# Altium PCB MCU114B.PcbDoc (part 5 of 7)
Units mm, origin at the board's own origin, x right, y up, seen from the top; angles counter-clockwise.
Board outline 105.51 x 58.76 mm, 8 copper layers (Top Layer, GND 2, Signal Layer 3, Power 4, Power 5, Signal Layer 6, GND 7, Bottom), stack 1.554 mm thick; 444 components, 418 nets, 1811 pads, 981 vias.
Unrouted connection lines stored in the file: 3.
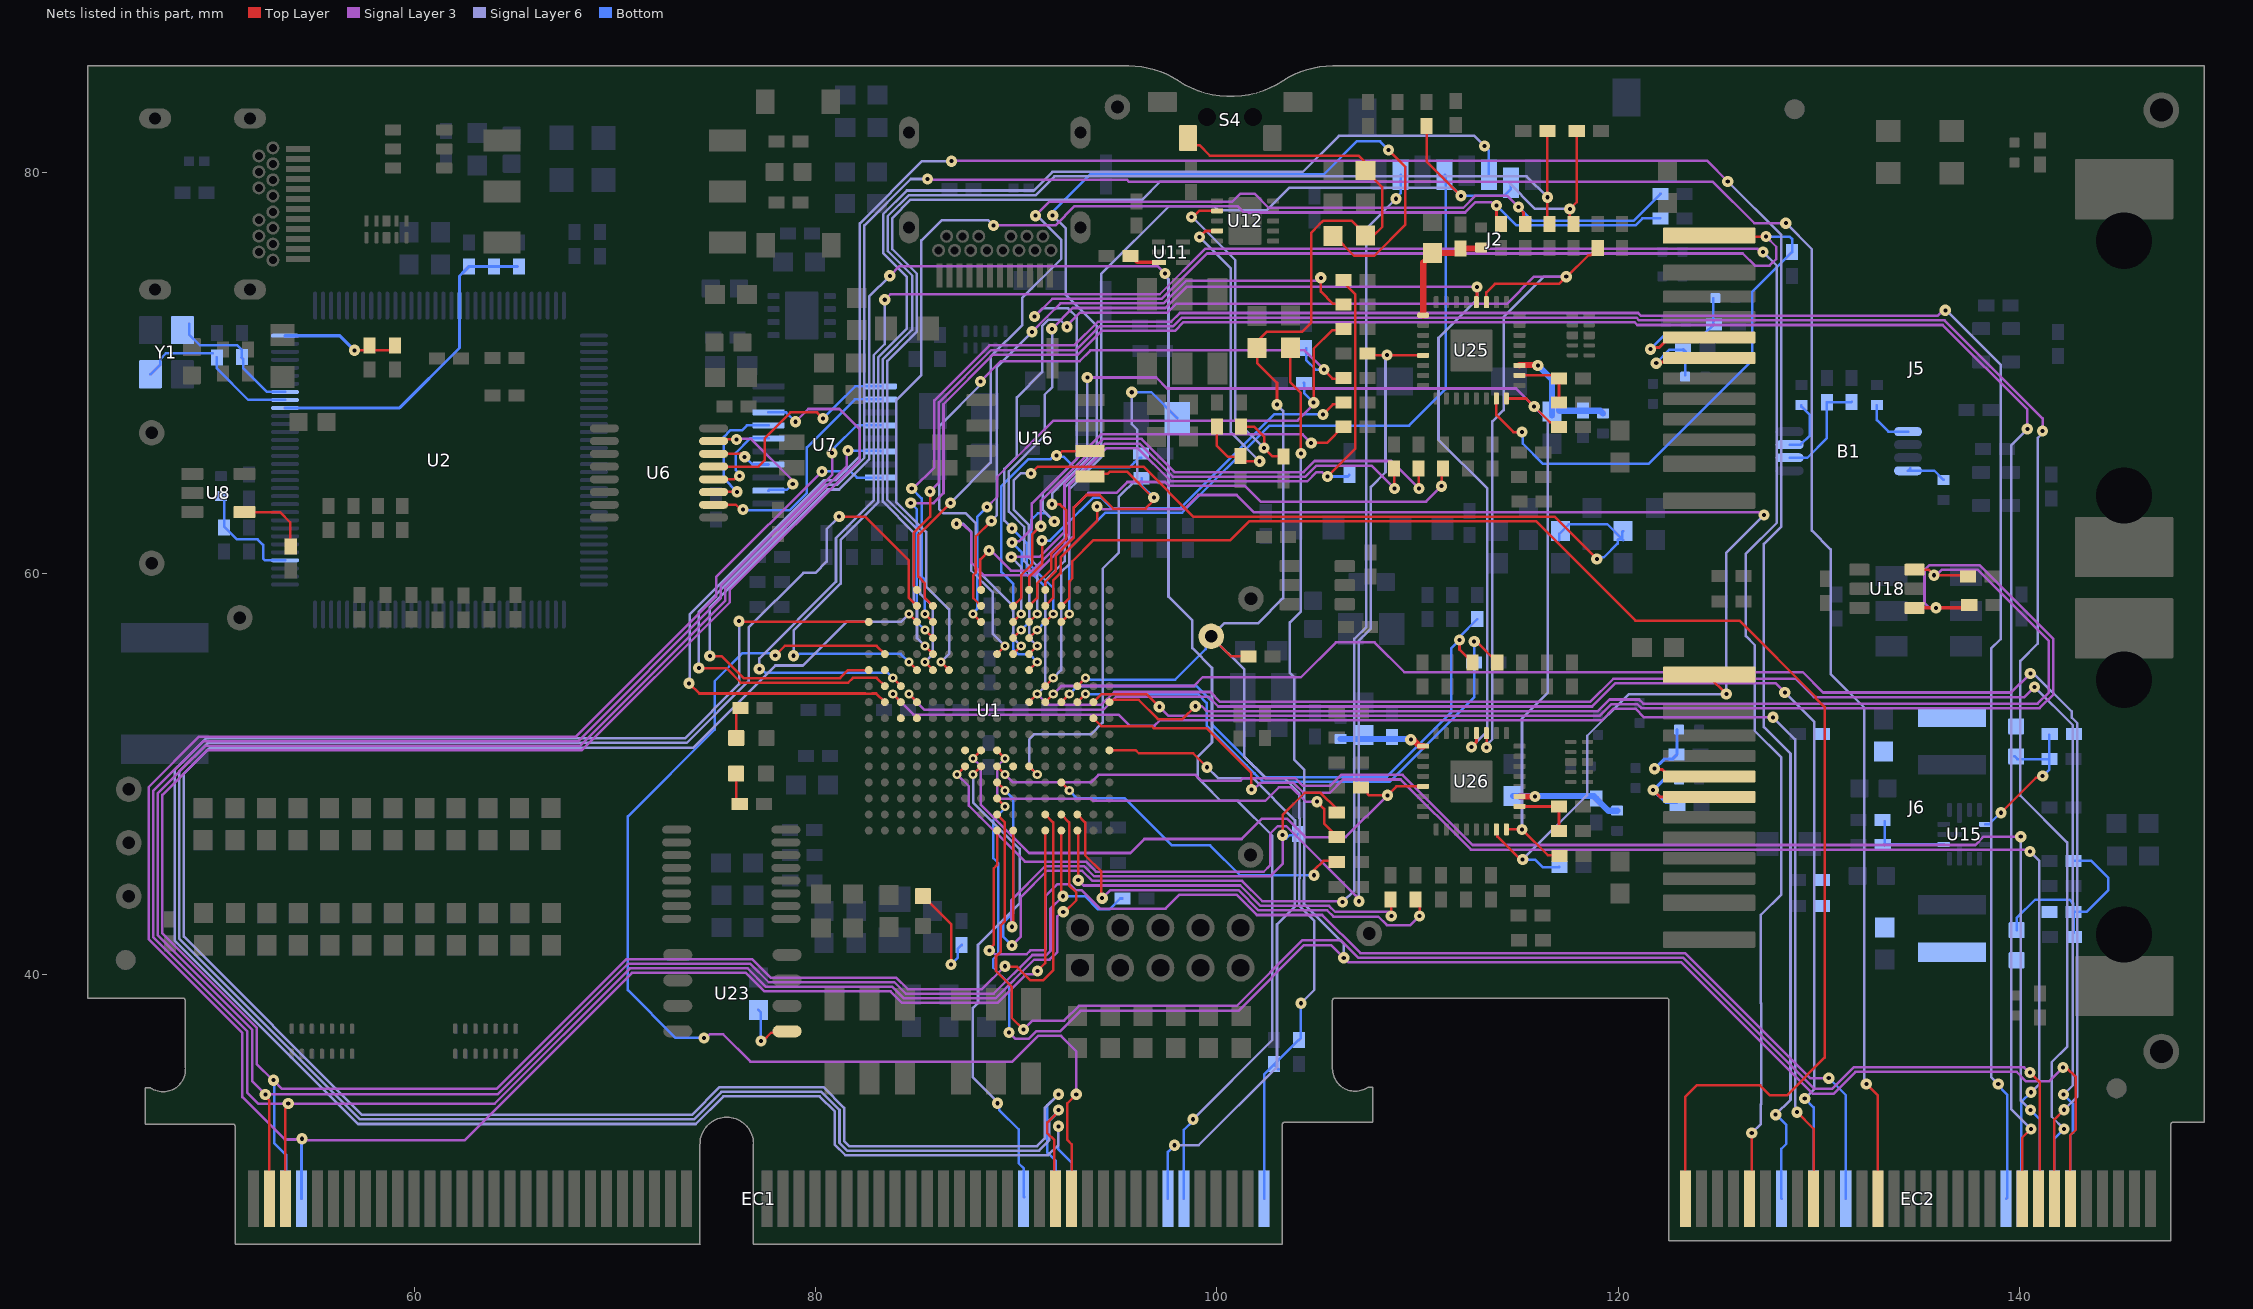
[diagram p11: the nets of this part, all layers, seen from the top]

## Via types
v1: diameter 0.559, hole 0.203, Top Layer to Bottom, tented both sides, 810 vias
v2: diameter 0.457, hole 0.203, Top Layer to Bottom, tented both sides, 153 vias
v3: diameter 0.5, hole 0.2, Top Layer to Bottom, tented both sides, 10 vias
v4: diameter 0.5, hole 0.2, Top Layer to Bottom, tented bottom, 4 vias
v5: diameter 0.5, hole 0.2, Top Layer to Bottom, tented top, 4 vias

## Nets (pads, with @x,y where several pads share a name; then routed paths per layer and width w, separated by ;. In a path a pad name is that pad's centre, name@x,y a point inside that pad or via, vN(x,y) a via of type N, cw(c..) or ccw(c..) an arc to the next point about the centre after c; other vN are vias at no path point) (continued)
MCU_GPIO93: EC2.162 U1.C5 | length 110.4
  Top Layer w0.127: v2(85.441,57.995) U1.C5@85.841,57.595
  Signal Layer 3 w0.127: v1(84.785,64.249) 84.853,64.249 85.911,65.307 85.911,68.639 88.653,71.381 90.23,71.381 92.881,71.381 94.062,72.562 97.718,72.562 98.155,73 121.006,73 121.147,72.859 135.926,72.859 136.201,73.133 v1(136.318,73.133)
  Signal Layer 6 w0.127: v1(136.318,73.133) 136.368,73.133 139.074,70.427 139.074,56.732 138.606,56.264 138.606,34.904 v1(138.959,34.551)
  Bottom w0.127: v1(84.785,64.249) 85.278,63.756 85.278,59.865 85.441,59.701 v2(85.441,57.995) ; v1@138.883,34.551 139.404,34.03 139.404,28.885 EC2.162@139.355,28.836
MCU_GPIO94: EC2.163 U1.D5 | length 111.1
  Top Layer w0.127: v2(85.441,57.195) U1.D5@85.841,56.795 ; EC2.163@140.155,28.836 140.155,31.886 v1(140.585,32.316)
  Signal Layer 3 w0.127: v1(84.736,63.525) 85.877,63.525 86.368,64.016 86.368,68.45 88.842,70.924 90.041,70.924 93.07,70.924 94.252,72.105 97.907,72.105 98.344,72.542 120.817,72.542 120.958,72.402 136.186,72.402 140.407,68.18 v1(140.407,67.215)
  Signal Layer 6 w0.127: v1(140.407,67.215) 139.608,66.416 139.608,33.293 v1(140.585,32.316)
  Bottom w0.127: v1@84.836,63.424 85.035,63.225 85.035,57.601 v2(85.441,57.195)
MCU_GPIO95: EC2.168 U1.A4 | length 109.9
  Top Layer w0.127: U1.A4@85.041,59.195 85.041,59.247 84.883,59.406 84.883,62.027 85.7,62.844 v1(85.7,64.107)
  Signal Layer 3 w0.127: v1(85.7,64.107) 86.14,64.547 86.14,68.545 88.748,71.152 90.136,71.152 92.975,71.152 94.157,72.334 97.812,72.334 98.25,72.771 120.912,72.771 121.053,72.63 136.28,72.63 141.169,67.742 v1(141.169,67.114)
  Signal Layer 6 w0.127: v1(141.169,67.114) 141.169,67.014 140.928,66.773 140.928,56.516 140.065,55.653 140.065,48.93 142.388,46.606 142.388,36.411 141.626,35.649 141.626,32.925 v1(142.236,32.316)
  Bottom w0.127: EC2.168@141.755,28.836 141.755,31.835 v1(142.236,32.316)
MCU_GPIO96: EC1.93 U1.B4 | length 112.3
  Top Layer w0.127: v1(81.168,62.852) 82.462,62.852 84.632,60.682 84.632,59.033 84.632,58.804 U1.B4@85.041,58.395 ; EC1.93@91.957,28.836 91.893,28.9 91.893,31.756 91.55,32.099 91.55,32.643 92.096,33.189 v1(92.096,33.255)
  Signal Layer 6 w0.127: v1@81.085,62.759 80.543,62.217 80.543,60.604 79.981,60.042 79.377,60.042 76.653,57.317 76.653,54.649 73.566,51.562 49.694,51.562 48.26,50.128 48.26,41.808 57.277,32.791 73.921,32.791 75.299,34.17 80.284,34.17 81.182,33.272 81.182,31.619 81.565,31.236 91.132,31.236 91.651,31.755 91.651,32.743 92.096,33.189 v1(92.096,33.255)
MCU_GPIO97: EC1.94 U1.C4 | length 105.8
  Top Layer w0.127: v2(84.641,57.995) U1.C4@85.041,57.595
  Signal Layer 6 w0.127: v2(84.641,57.995) 84.241,57.595 81.53,57.595 79.358,55.423 77.986,55.423 73.896,51.333 49.789,51.333 48.489,50.033 48.489,41.903 57.371,33.02 73.826,33.02 75.205,34.398 80.378,34.398 81.41,33.366 81.41,31.714 81.659,31.465 91.037,31.465 91.41,31.838 91.41,33.357 v1(92.096,34.043)
  Bottom w0.127: EC1.94@91.957,28.836 91.969,28.848 91.969,30.715 91.55,31.135 91.55,33.497 v1(92.096,34.043)
MCU_GPIO98: EC1.95 U1.E2 | length 59.1
  Top Layer w0.127: v1(77.978,55.931) 78.452,56.404 83.032,56.404 U1.E2@83.441,55.995 ; EC1.95@92.757,28.836 92.757,31.553 92.541,31.77 92.541,33.598 v1(92.985,34.043)
  Signal Layer 3 w0.127: v1(74.422,36.855) 74.534,36.855 74.712,37.033 75.387,37.033 76.746,35.674 89.802,35.674 91.084,36.957 92.227,36.957 92.985,36.199 v1(92.985,34.043)
  Bottom w0.127: v1(74.422,36.855) 73.011,36.855 70.631,39.236 70.631,47.895 74.964,52.228 74.964,54.648 76.355,56.039 77.87,56.039 v1(77.978,55.931)
MCU_GPIO99: EC1.96 U1.C1 | length 103.9
  Top Layer w0.127: v1(76.175,57.633) 76.212,57.595 U1.C1@82.641,57.595
  Signal Layer 6 w0.127: v1(76.175,57.633) 76.175,54.494 73.471,51.791 49.599,51.791 48.031,50.223 48.031,41.713 57.182,32.563 74.016,32.563 75.394,33.941 80.189,33.941 80.953,33.177 80.953,31.524 81.47,31.008 91.586,31.008 92.095,31.516 v1(92.095,32.448) v1@92.095,32.559
  Bottom w0.127: v1@92.096,32.558 92.096,31.297 92.757,30.636 EC1.96@92.757,28.836
MCU_GPIO100: J2.3 U1.F4 | length 64.7
  Top Layer w0.127: v2(84.641,55.595) U1.F4@85.041,55.195
  Signal Layer 6 w0.127: v1(78.894,55.909) 78.894,57.163 81.238,59.506 81.238,61.687 83.117,63.566 83.117,70.798 84.547,72.228 84.547,74.801 83.359,75.99 83.359,77.923 84.544,79.108 90.875,79.108 91.803,80.035 104.281,80.035 106.079,81.833 112.833,81.833 v1(113.335,81.331)
  Bottom w0.127: v1(78.894,55.909) 78.977,55.992 79.175,55.992 79.184,56.001 84.235,56.001 v2(84.641,55.595) ; v1(113.335,81.331) 113.557,81.108 J2.3@113.557,79.893
MCU_GPIO101: J2.7 U1.N9 | length 66.1
  Top Layer w0.127: U1.N9@89.041,49.595 89.43,49.206 v2@89.43,49.192
  Signal Layer 3 w0.127: v1(89.785,41.47) 89.792,41.47 90.229,41.907 90.229,43.885 91.535,45.191 93.282,45.191 93.79,44.683 101.258,44.683 102.272,43.669 106.226,43.669 v1(106.267,43.628)
  Signal Layer 6 w0.127: v1(106.267,43.628) 106.854,44.214 106.854,56.757 107.45,57.354 107.45,77.21 v1(108.936,78.696)
  Bottom w0.127: v2(89.441,49.195) 89.841,48.795 89.841,48.28 89.841,48.121 ; v1(89.785,41.47) 89.34,41.915 89.34,42.584 89.841,43.085 89.841,48.121 ; v1(108.936,78.696) 108.936,78.749 109.157,78.97 J2.7@109.157,79.893
MCU_GPIO102: J2.5 U1.C13 | length 36.6
  Top Layer w0.127: U1.C13@92.241,57.595 v2(92.641,57.995)
  Bottom w0.127: v2(92.641,57.995) 92.641,61.248 94.436,63.043 98.273,63.043 102.616,67.386 109.584,67.386 111.4,69.202 111.4,78.721 111.4,79.85 J2.5@111.357,79.893
MCU_GPIO103: J2.2 R36.1 U1.G12 | length 48.9
  Top Layer w0.127: U1.G12@91.441,54.395 v2(91.841,54.795) ; R36.1@110.452,82.323 110.452,80.556 v1(112.166,78.842)
  Signal Layer 6 w0.127: v2(91.841,54.795) 92.235,55.189 92.235,60.082 92.642,60.489 92.642,64.211 94.23,65.798 94.23,74.94 97.61,78.321 99.865,78.321 100.062,78.124 102.49,78.124 103.602,79.235 111.773,79.235 v1(112.166,78.842)
  Bottom w0.127: v1(112.166,78.842) 114.321,78.842 114.657,79.178 J2.2@114.657,79.493
MCU_GPIO104: EC2.121 U1.B13 | length 75.4
  Top Layer w0.127: U1.B13@92.241,58.395 92.642,58.795 92.641,59.622 92.788,59.768 92.788,60.618 93.842,61.671 100.675,61.671 101.609,62.605 115.931,62.605 120.872,57.665 126.056,57.665 129.855,53.865 129.855,53.808 130.302,53.361 130.302,35.876 128.418,33.992 127.58,33.992 127.081,34.491 123.922,34.491 123.355,33.923 EC2.121@123.355,28.836
MCU_GPIO105: EC1.108 U1.L16 | length 32.9
  Top Layer w0.127: U1.L16@94.641,51.195 95.956,51.195 96.103,51.048 97.995,51.048 98.814,51.048 v1(99.513,50.35)
  Signal Layer 6 w0.127: v1(97.887,31.503) 99.092,31.503 102.997,35.408 102.997,42.52 103.886,43.409 103.886,44.907 103.894,44.916 103.894,47.701 101.792,49.804 100.059,49.804 v1(99.513,50.35)
  Bottom w0.127: EC1.108@97.557,28.836 97.557,31.173 v1(97.887,31.503)
MCU_GPIO106: EC1.110 U1.F1 | length 96.9
  Top Layer w0.127: v1(74.717,55.896) 75.295,55.896 76.398,54.793 81.209,54.793 81.61,55.194 81.929,55.194 ; 81.93,55.195 U1.F1@82.641,55.195
  Signal Layer 3 w0.127: v1(83.693,74.854) 84.176,75.336 97.043,75.336 v1(97.416,74.963)
  Signal Layer 6 w0.127: v1(74.717,55.896) 74.717,58.334 80.582,64.199 81.161,64.199 82.66,65.697 82.66,73.821 v1(83.693,74.854) ; v1(97.416,74.963) 97.416,74.847 97.587,74.676 97.587,58.854 98.776,57.665 98.776,56.287 99.754,55.309 99.754,51.588 99.034,50.867 99.034,49.832 99.399,49.467 100.192,48.673 101.03,48.673 102.768,46.935 102.768,36.765 v1(98.802,32.798)
  Bottom w0.127: EC1.110@98.357,28.836 98.357,32.277 98.802,32.722 v1(98.802,32.798)
MCU_GPIO107: U1.F2
MCU_GPIO108: EC2.145 U1.G2 | length 134
  Top Layer w0.127: v1(74.168,55.296) 75.54,55.296 76.271,54.564 81.615,54.564 81.855,54.804 83.032,54.804 U1.G2@83.441,54.395 ; v1(132.381,34.551) 132.955,33.977 EC2.145@132.955,28.836
  Signal Layer 3 w0.127: v1(85.573,79.68) 85.604,79.649 95.507,79.649 95.602,79.553 124.717,79.553 126.793,77.477 v1(128.367,77.477)
  Signal Layer 6 w0.127: v1(74.168,55.296) 74.168,58.108 80.487,64.427 81.067,64.427 82.423,65.783 82.423,77.368 84.735,79.68 v1(85.573,79.68) ; v1(128.367,77.477) 129.667,76.177 129.667,62.15 130.603,61.214 130.603,54.998 132.283,53.317 132.283,34.648 v1(132.381,34.551)
MCU_GPIO109: EC2.129 U1.G3 | length 122.8
  Top Layer w0.127: v2(83.841,54.795) U1.G3@84.241,54.395 ; EC2.129@126.555,28.836 126.666,28.947 v1(126.666,32.112)
  Signal Layer 3 w0.127: v1(83.439,73.66) 83.451,73.66 83.725,73.934 97.149,73.934 99.41,76.195 126.964,76.195 127.112,76.048 v1(127.229,76.048)
  Signal Layer 6 w0.127: v1(77.186,55.252) 77.186,55.778 81.009,59.601 81.009,61.781 82.889,63.661 82.889,70.893 83.439,71.443 v1(83.439,73.66) ; v1(126.666,32.112) 127.127,32.574 127.127,33.545 127.135,33.554 127.135,38.588 127.127,38.596 127.127,42.995 128.143,44.011 128.143,50.842 126.818,52.167 126.818,56.443 126.373,56.888 126.373,60.999 127.914,62.54 127.914,75.362 v1(127.229,76.048)
  Bottom w0.127: v1(77.186,55.252) 77.292,55.252 77.477,55.067 83.569,55.067 v2(83.841,54.795)
MCU_GPIO110: EC2.134 U1.H2 | length 135.3
  Top Layer w0.127: v1(73.685,54.534) 74.192,54.027 82.457,54.027 82.48,54.004 82.803,54.004 82.826,54.027 83.009,54.027 U1.H2@83.441,53.595
  Signal Layer 3 w0.127: v1(86.766,80.569) 86.779,80.581 124.45,80.581 v1(125.472,79.56)
  Signal Layer 6 w0.127: v1(73.685,54.534) 73.724,54.572 73.724,57.987 80.392,64.656 80.972,64.656 82.194,65.878 82.194,77.462 85.301,80.569 v1(86.766,80.569) ; v1(125.472,79.56) 128.143,76.888 128.143,62.349 127.275,61.481 127.275,52.356 128.278,51.353 128.6,51.031 128.6,33.768 v1(127.859,33.027)
  Bottom w0.127: v1(127.859,33.027) 127.885,33.027 128.393,32.519 128.393,31.579 128.139,31.325 128.139,28.852 EC2.134@128.155,28.836
MCU_GPIO111: EC2.137 U1.H3 | length 70.5
  Top Layer w0.127: v2(83.841,53.995) U1.H3@84.241,53.595 ; v1(128.926,33.154) 129.755,32.325 EC2.137@129.755,28.836
  Signal Layer 3 w0.127: v2(83.841,53.995) 84.864,52.972 95.093,52.972 95.64,52.426 96.897,52.426 97.166,52.694 119.187,52.694 119.764,53.271 120.864,53.271 121.296,52.839 v1(127.732,52.839)
  Signal Layer 6 w0.127: v1(127.732,52.839) 128.829,51.742 128.829,33.444 128.843,33.429 128.843,33.236 v1(128.926,33.154)
MCU_GPIO112: EC2.138 U1.H4 | length 71.9
  Top Layer w0.127: v2(84.641,53.995) U1.H4@85.041,53.595
  Signal Layer 3 w0.127: v2(84.641,53.995) 85.423,53.214 94.334,53.214 94.994,53.873 99.575,53.873 100.068,53.38 118.705,53.38 119.859,54.534 127.866,54.534 v1(128.317,54.083)
  Signal Layer 6 w0.127: v1(128.317,54.083) 129.794,52.606 129.794,34.315 v1(129.311,33.833)
  Bottom w0.127: v1(129.311,33.833) 129.755,33.39 EC2.138@129.755,28.836
MCU_GPIO113: U1.J3 | length 0
MCU_GPIO114: U1.J4
MCU_GPIO115: EC2.169 R212.1 U1.P9 | length 110.3
  Top Layer w0.127: U1.P9@89.041,48.795 v2(89.441,48.395) ; R212.1@103.658,71.267 103.658,69.538 104.191,69.006 v1(104.191,65.989) ; v1(142.189,35.382) 142.344,35.382 142.824,34.902 142.824,32.275 142.555,32.006 EC2.169@142.555,28.836
  Signal Layer 3 w0.127: v1(89.638,37.124) 89.957,36.805 90.609,36.805 90.99,37.186 92.177,37.186 93.199,38.208 101.067,38.208 104.336,41.478 105.698,41.478 v1(106.326,40.85) 106.555,40.621 123.16,40.621 129.701,34.081 130.761,34.081 131.84,35.16 139.88,35.16 140.35,34.691 141.498,34.691 v1(142.189,35.382)
  Signal Layer 6 w0.127: v1(104.191,65.989) 104.191,58.12 103.64,57.57 103.64,55.059 103.85,54.849 103.85,50.735 104.352,50.234 104.352,44.718 104.343,44.709 104.343,43.531 106.326,41.548 v1(106.326,40.85)
  Bottom w0.127: v2(89.441,48.395) 89.441,48.306 88.849,47.713 88.849,45.817 89.098,45.568 89.098,41.034 88.849,40.785 88.849,40.354 89.638,39.565 v1(89.638,37.124) ; v1@89.56,37.16 v1@89.581,37.181
MCU_GPIO116: EC2.170 R78.1 U1.H11 | length 131.9
  Top Layer w0.127: U1.H11@90.641,53.595 v2(91.041,53.995) ; R78.1@105.871,76.829 106.849,75.851 107.844,75.851 109.398,77.405 109.398,80.289 v1(108.56,81.128)
  Signal Layer 3 w0.127: v2(91.041,53.995) 91.564,53.473 94.253,53.473 94.883,54.102 99.67,54.102 100.163,53.609 118.61,53.609 119.764,54.762 128.854,54.762 129.769,53.848 140.259,53.848 v1(140.767,54.356)
  Signal Layer 6 w0.127: v2(91.041,53.995) 91.448,54.401 91.448,59.666 92.414,60.632 92.414,64.306 94.001,65.893 94.001,72.369 92.47,73.901 92.47,77.208 v1(91.81,77.867) ; v1(140.767,54.356) 142.672,52.451 142.672,34.493 v1(142.215,34.036)
  Bottom w0.127: v1@91.722,77.955 93.678,79.911 105.326,79.911 106.968,81.554 108.134,81.554 v1(108.56,81.128) ; v1(142.215,34.036) 142.684,33.566 142.684,32.136 142.555,32.006 EC2.170@142.555,28.836
MCU_GPIO119: U1.M10
MCU_GPIO120: R85.2 U1.M11 | length 26.6
  Top Layer w0.127: U1.M11@90.641,50.395 v2(91.041,49.995)
  Signal Layer 6 w0.127: v2(91.041,49.995) 90.648,50.389 90.648,51.758 90.878,51.989 93.604,51.989 93.717,51.989 94.306,52.578 94.306,60.249 95.1,61.043 95.1,63.814 96.032,64.746 96.032,67.177 95.756,67.453 v1(95.756,69.047)
  Bottom w0.127: v1(95.756,69.047) 96.732,69.047 R85.2@98.014,67.764
MCU_GPIO122: U1.L7 | length 0
MCU_GPIO123: R108.2 U1.M7 U25.21 | length 57.3
  Top Layer w0.127: v2(87.041,49.995) U1.M7@87.441,50.395 ; R108.2@107.494,70.934 107.541,70.887 U25.21@110.285,70.887
  Signal Layer 3 w0.127: v2(87.041,49.995) 87.626,49.411 87.626,48.445 90.422,45.649 93.472,45.649 93.972,45.149 100.421,45.149 100.429,45.141 102.337,45.141 102.656,45.46 102.656,47.035 103.03,47.409 103.461,47.409 106.936,43.934 ; 106.936,43.932 107.082,43.786 v1(107.082,43.669)
  Signal Layer 6 w0.127: v1(107.082,43.669) 107.082,56.663 107.679,57.26 107.679,64.332 108.406,65.059 108.406,70.825 v1(108.479,70.898)
MCU_GPIO124: R142.2 U1.L8 U26.21 | length 29.8
  Top Layer w0.127: v2(87.841,50.795) U1.L8@88.241,51.195 ; R142.2@107.175,49.347 107.275,49.347 107.512,49.111 107.512,49.027 107.586,48.953 v1(108.505,48.953) 108.951,49.399 U26.21@110.285,49.399
  Signal Layer 3 w0.127: v2(87.841,50.795) 88.235,50.401 88.235,48.477 90.637,46.076 95.682,46.076 96.379,46.773 101.231,46.773 102.242,47.784 103.487,47.784 104.408,46.864 106.416,46.864 v1(108.505,48.953)
MCU_GPIO125: EC1.90 U1.M8 | length 24.6
  Top Layer w0.127: v2(87.841,49.995) U1.M8@88.241,50.395
  Signal Layer 6 w0.127: v2(87.841,49.995) 87.841,48.604 90.166,46.279 90.166,43.568 88.087,41.489 88.087,38.601 87.833,38.347 87.833,34.885 v1@89.058,33.66
  Bottom w0.127: v1(89.059,33.599) 89.14,33.519 89.14,33.269 90.119,32.29 90.119,30.604 90.371,30.352 90.371,28.936 EC1.90@90.384,28.923
MCU_GPIO126: EC2.142 U1.T9 | length 62
  Top Layer w0.127: v1(88.654,41.218) 88.654,41.278 88.884,41.508 88.884,45.314 89.041,45.472 U1.T9@89.041,47.195
  Signal Layer 3 w0.127: v1(88.654,41.218) 88.752,41.218 88.944,41.026 90.512,41.026 90.704,41.218 91.399,41.218 91.473,41.292 91.473,43.95 92.05,44.526 92.654,44.526 92.961,44.219 93.254,44.219 94.173,43.301 97.436,43.301 98.133,43.998 100.974,43.998 101.988,42.984 105.251,42.984 107.156,41.079 123.35,41.079 129.58,34.849 v1(130.505,34.849)
  Bottom w0.127: v1(130.505,34.849) 131.355,33.999 EC2.142@131.355,28.836
MCU_GPIO127: EC2.165 U1.R9 | length 73.9
  Top Layer w0.127: U1.R9@89.041,47.995 89.432,47.604 89.432,42.675 89.23,42.474 89.23,41.166 88.986,40.921 88.986,40.613 88.986,40.196 89.766,39.415 89.766,37.862 v1(90.36,37.268) ; v1(140.534,35.135) 141.029,34.64 141.029,28.836 EC2.165@140.955,28.836
  Signal Layer 3 w0.127: v1(90.36,37.268) 90.812,37.719 92.387,37.719 93.123,38.456 100.99,38.456 104.267,41.732 106.172,41.732 107.054,40.85 123.255,40.85 129.795,34.31 130.666,34.31 131.746,35.389 140.244,35.389 140.498,35.135 v1(140.534,35.135)
MCU_GPIO128: EC2.166 U1.M9 | length 72.2
  Top Layer w0.127: U1.M9@89.041,50.395 v2(89.441,49.995)
  Signal Layer 3 w0.127: v2(89.441,49.995) 89.835,49.601 93.729,49.601 94.097,49.969 98.942,49.969 99.234,49.677 101.177,49.677 101.304,49.804 103.907,49.804 104.292,49.418 105.648,49.418 106.198,49.969 109.26,49.969 112.753,46.475 137.816,46.475 138.229,46.888 v1(140.081,46.888)
  Signal Layer 6 w0.127: v1(140.081,46.888) 140.089,46.88 140.089,33.725 v1(140.559,33.255)
  Bottom w0.127: v1(140.559,33.255) 141.029,32.786 141.029,28.91 EC2.166@140.955,28.836
MCU_GPIO129: R91.2 U1.L9 | length 21.4
  Top Layer w0.127: U1.L9@89.041,51.195 v2(89.441,50.795) ; v1(104.987,48.633) 105.342,48.278 105.342,47.536 R91.2@105.961,46.917 ; R91.2@106.194,47.041 R91.2@106.294,47.041
  Signal Layer 3 w0.127: 89.048,50.27 89.048,48.92 89.179,48.789 93.733,48.789 93.848,48.673 102.411,48.673 103.084,49.346 103.342,49.346 103.717,49.346 104.431,48.633 v1(104.987,48.633) ; 89.048,50.27 89.048,50.402 v2(89.441,50.795)
MCU_GPIO130: R146.2 R155.1 U1.T10 | length 27.6
  Top Layer w0.127: v1(89.785,42.399) 89.836,42.45 89.836,45.443 89.841,45.449 U1.T10@89.841,47.195 ; v1@103.29,46.965 103.29,47.991 104.379,49.08 104.381,49.077 105.171,49.077 105.961,48.287 R155.1@105.961,48.122
  Signal Layer 3 w0.127: v1(89.785,42.399) 89.737,42.447 89.737,43.716 91.441,45.42 93.377,45.42 93.885,44.912 102.658,44.912 103.276,45.531 v1(103.276,46.965)
  Bottom w0.127: v1@103.454,46.787 103.628,46.961 103.981,46.961 R146.2@104.044,47.024
MCU_GPIO131: R203.2 U1.N13 | length 16.5
  Top Layer w0.127: U1.N13@92.241,49.595 v2(92.641,49.195) ; v1(104.847,44.965) 104.847,45.221 105.311,45.686 105.935,45.686 R203.2@105.961,45.712 ; R203.2@106.014,45.659 106.194,45.839 R203.2@106.294,45.839
  Bottom w0.127: v2(92.641,49.195) 93.033,48.803 93.277,48.803 93.278,48.801 93.604,48.801 93.606,48.803 95.412,48.803 97.756,46.459 99.656,46.459 101.15,44.965 v1(104.847,44.965)
MCU_GPIO132: R144.2 U1.T14 | length 19.9
  Top Layer w0.127: U1.T14@93.041,47.195 93.081,47.156 93.081,44.754 v1@93.113,44.721 ; R144.2@108.661,43.774 108.697,43.738 v1(108.697,42.941)
  Signal Layer 3 w0.127: v1(93.088,44.721) 93.354,44.455 101.163,44.455 102.177,43.441 105.595,43.441 105.9,43.136 108.57,43.136 108.773,42.933 v1@108.86,42.933
MCU_GPIO133: EC2.164 U1.J15 | length 68.5
  Top Layer w0.127: U1.J15@93.841,52.795 94.241,52.395 96.768,52.395 96.87,52.292 99.498,52.292 101.72,50.07 v1(101.72,49.246)
  Signal Layer 3 w0.127: v1@101.848,49.259 102.163,49.575 103.812,49.575 104.307,49.08 105.633,49.08 106.293,49.74 109.165,49.74 112.658,46.247 140.443,46.247 v1(140.538,46.152)
  Signal Layer 6 w0.127: v1(140.538,46.152) 141.004,45.686 141.004,34.564 v1(140.585,34.144)
  Bottom w0.127: EC2.164@140.155,28.836 140.115,28.876 140.115,33.675 v1(140.585,34.144)
MCU_GPIO134: R110.2 U1.R14 | length 22.5
  Top Layer w0.127: U1.R14@93.041,47.995 93.432,47.604 93.432,45.963 94.243,45.152 94.243,43.859 v1(94.281,43.822) ; v1@110.044,42.994 v1(110.105,42.933) 110.105,43.705 R110.2@110.044,43.766
  Signal Layer 3 w0.127: v1(94.281,43.822) 94.685,44.226 101.069,44.226 102.083,43.212 105.5,43.212 105.805,42.907 108.045,42.907 108.477,42.476 109.648,42.476 v1(110.105,42.933)
MCU_GPIO141: R145.1 R152.1 U1.H13 | length 30.2
  Top Layer w0.127: U1.H13@92.241,53.595 v2(92.641,53.995) ; v1(112.096,56.697) 112.096,56.215 R152.1@112.738,55.572
  Bottom w0.127: v2(92.641,53.995) 93.048,54.401 98.975,54.401 99.754,53.621 99.754,52.488 101.705,50.537 101.705,50.528 101.966,50.268 101.974,50.268 102.382,49.86 108.46,49.86 111.68,53.08 111.68,56.281 v1(112.096,56.697) 112.096,56.852 R145.1@112.98,57.736
MCU_GPIO142: R133.1 R153.1 U1.H14 | length 28.5
  Top Layer w0.127: U1.H14@93.041,53.595 v2(93.441,53.995) ; v1(112.827,56.617) 112.934,56.617 R153.1@113.978,55.572
  Bottom w0.127: v2(93.441,53.995) 99.058,53.995 99.492,53.561 99.492,52.427 101.477,50.442 101.477,50.434 101.871,50.039 101.879,50.039 102.287,49.632 108.627,49.632 112.828,53.833 R133.1@112.828,55.572 112.828,56.615 v1(112.827,56.617)
MCU_GPIO145: R139.1 U1.H15 U18.1 | length 65
  Top Layer w0.127: U1.H15@93.841,53.595 94.241,53.995 96.5,53.995 v1(97.13,53.365)
  Top Layer w0.159: U18.1@134.787,58.3 v1(135.86,58.3) 137.373,58.3 R139.1@137.511,58.437
  Signal Layer 3 w0.127: v1(97.13,53.365) 97.13,53.361 97.567,52.923 119.093,52.923 119.669,53.499 120.959,53.499 121.162,53.296 141.017,53.296 141.707,53.986 141.707,56.739 138.017,60.429 135.533,60.429 135.28,60.176 135.28,58.531 135.481,58.331 135.829,58.331 v1(135.86,58.3)
MCU_GPIO146: R140.1 U1.H16 U18.3 | length 60.9
  Top Layer w0.127: U1.H16@94.641,53.595 94.715,53.595 94.836,53.715 96.094,53.715 97.06,52.749 98.281,52.749 v1(98.925,53.393) ; U18.3@134.787,60.2 135.477,60.2 135.752,59.925 137.394,59.925 R140.1@137.46,59.86
  Signal Layer 3 w0.127: v1(98.925,53.393) 99.25,53.393 99.492,53.152 118.998,53.152 119.574,53.728 121.053,53.728 121.257,53.525 140.922,53.525 141.478,54.081 141.478,56.645 137.922,60.2 136.148,60.2 135.874,59.925 v1(135.759,59.925)
MCU_GPIO147: EC2.167 U1.H12 | length 79.5
  Top Layer w0.127: U1.H12@91.441,53.595 v2(91.841,53.995) ; EC2.167@141.755,28.836 141.755,32.797 142.232,33.274 v1(142.24,33.274)
  Signal Layer 3 w0.127: v2(91.841,53.995) 92.248,54.401 98.851,54.401 99.289,54.839 104.191,54.839 105.927,56.575 107.863,56.575 109.351,55.087 126.644,55.087 126.65,55.093 129.21,55.093 130.226,54.077 139.601,54.077 v1(140.557,55.032)
  Signal Layer 6 w0.127: v1(140.557,55.032) 140.719,55.032 142.621,53.13 142.621,52.825 142.9,52.546 142.9,33.934 v1(142.24,33.274)
MCU_GPIO148: J5.1 R129.2 U1.C12 U25.31 | length 88.9
  Top Layer w0.127: U1.C12@91.441,57.595 v2(91.841,57.995) ; U25.31@113.935,68.737 113.935,67.912 114.442,67.406 114.785,67.063 v1(115.21,67.063) ; J5.1@124.544,76.858 124.593,76.81 v1(127.381,76.81)
  Signal Layer 3 w0.127: v1(90.907,72.822) 91.79,73.705 97.244,73.705 99.505,75.966 126.218,75.966 126.822,75.362 127.559,75.362 127.889,75.692 127.889,76.302 v1(127.381,76.81)
  Signal Layer 6 w0.127: v1(90.907,72.822) 91.313,73.228 92.586,73.228 93.011,72.802 93.011,65.703 91.309,64.001 91.309,63.199 91.893,62.615 v1(91.893,62.601)
  Bottom w0.127: v2(91.841,57.995) 91.841,59.276 90.742,60.376 90.742,61.241 90.742,62.686 91.067,63.011 91.483,63.011 v1(91.893,62.601) ; v1(115.21,67.063) 115.251,67.022 115.251,66.479 116.242,65.488 121.535,65.488 126.7,70.654 126.7,74.062 R129.2@128.676,76.038 128.676,76.688 128.555,76.81 v1(127.381,76.81)
MCU_GPIO149: J6.1 R163.1 U1.B12 U26.31 | length 70.5
  Top Layer w0.127: U1.B12@91.441,58.395 91.851,58.804 91.851,59.68 92.203,60.033 92.203,60.81 94.027,62.633 v1(94.027,63.354) ; U26.31@113.935,47.249 113.986,47.198 113.986,46.889 115.129,45.746 v1(115.246,45.746) ; J6.1@124.544,54.972 124.544,54.856 v1(125.4,54)
  Signal Layer 3 w0.127: v1(94.027,63.354) 94.143,63.354 94.289,63.208 98.362,63.208 99.079,63.926 100.984,63.926 101.847,63.062 127.019,63.062 127.158,62.923 v1(127.275,62.923)
  Signal Layer 6 w0.127: v1(115.246,45.746) 118.466,48.966 118.466,51.922 120.544,54 v1(125.4,54) 125.4,61.047 v1(127.275,62.923)
  Bottom w0.127: v1(115.246,45.746) 115.856,45.746 116.248,45.355 117.049,45.355 R163.1@117.074,45.38
MCU_GPIO150: R105.1 U1.A12 U16.5 | length 14.2
  Top Layer w0.127: U1.A12@91.441,59.195 91.441,59.594 91.975,60.127 91.975,60.905 92.871,61.801 92.871,63.31 93.487,63.926 94.154,63.926 94.84,63.24 94.844,63.244 96.442,63.244 96.901,63.703 95.517,65.087 94.659,65.087 94.545,64.973 94.269,64.973 U16.5@94.16,65.083 ; U16.5@93.469,64.762 U16.5@93.469,64.83
  Bottom w0.127: R105.1@96.25,64.76 96.25,64.398 v1(96.855,63.794)
MCU_GPIO151: R106.1 U1.F11 U16.6 | length 20.2
  Top Layer w0.127: U1.F11@90.641,55.195 v2(91.041,55.595) ; v1(92,65.888) 92.061,65.888 92.29,66.116 U16.6@93.682,66.116
  Bottom w0.127: v2(91.041,55.595) 90.648,55.989 90.091,55.989 89.848,56.232 89.848,59.487 89.256,60.079 89.256,64.364 90.609,65.717 91.712,65.717 91.883,65.888 v1(92,65.888) 92.052,65.835 92.358,65.835 92.876,65.316 95.657,65.316 95.888,65.547 95.888,65.55 96.125,65.786 R106.1@96.225,65.786
MCU_GPIO152: U1.E11 U25.12 U26.12 | length 66.6
  Top Layer w0.127: U1.E11@90.641,55.995 v2(91.041,56.395)
  Top Layer w0.159: v1(112.696,51.366) 112.935,51.606 U26.12@112.935,52.049 ; U25.12@112.935,73.537 112.975,73.577 v1(112.975,74.302)
  Signal Layer 3 w0.127: v1(91.77,72.212) 92.806,73.248 97.433,73.248 98.487,74.302 v1(112.975,74.302)
  Signal Layer 6 w0.127: v2(91.041,56.395) 90.635,56.801 90.635,60.389 90.394,60.63 90.394,62.338 89.632,63.1 89.632,65.096 91.415,66.878 91.415,68.922 91.796,69.303 91.796,72.187 v1(91.77,72.212) ; v1(112.696,51.366) 113.487,52.157 113.487,64.239 111.049,66.678 111.049,71.755 112.975,73.681 v1(112.975,74.302)
MCU_GPIO153: R107.1 U1.D11 U25.11 U26.11 | length 78.3
  Top Layer w0.127: U1.D11@90.641,56.795 v2(91.041,57.195) ; U26.11@113.435,52.049 113.445,52.04 v1(113.445,51.338) ; U25.11@113.435,73.537 113.435,74.026 113.864,74.454 117.055,74.454 v1@117.415,74.815 ; v1(117.42,74.81) 117.456,74.81 118.526,75.88 118.626,75.88 118.863,76.116 R107.1@118.863,76.216
  Signal Layer 3 w0.127: v1(92.532,72.314) 92.532,72.372 93.179,73.019 97.528,73.019 97.966,73.457 114.462,73.457 115.815,74.81 v1(117.42,74.81)
  Signal Layer 6 w0.127: v1(89.785,62.262) 89.404,62.643 89.404,65.23 90.026,65.852 90.026,68.791 91.288,70.053 91.288,72.358 91.586,72.657 92.189,72.657 v1(92.532,72.314) ; v1(113.445,51.338) 113.445,51.455 113.737,51.747 113.737,67.59 114.3,68.153 114.3,72.808 116.302,74.81 v1(117.42,74.81)
  Bottom w0.127: v1(89.785,62.262) 90.509,61.538 90.509,60.286 91.435,59.359 91.435,57.589 v2(91.041,57.195)
MCU_GPIO154: R59.1 R64.1 U1.C11 | length 45.2
  Top Layer w0.127: U1.C11@90.641,57.595 v2(91.041,57.995) ; v1(90.729,64.999) 91.067,65.337 96.331,65.337 98.834,62.834 116.848,62.834 v1(118.944,60.738)
  Signal Layer 6 w0.127: v1(90.729,64.999) 90.213,64.999 89.861,64.647 89.861,63.195 90.623,62.433 90.623,60.802 91.041,60.383 v2(91.041,57.995)
  Bottom w0.127: R59.1@117.08,61.676 117.08,61.992 117.553,62.465 119.465,62.465 R64.1@120.203,61.728 ; v1(118.944,60.738) 119.027,60.821 119.296,60.821 119.98,61.505 119.98,61.685 120.023,61.728 R64.1@120.203,61.728 ; R64.1@120.255,61.676 R64.1@120.203,61.728 ; R64.1@120.255,62.121 120.203,62.069 R64.1@120.203,61.728
MCU_GPIO155: R32.1 R141.1 U1.B11 U25.32 U26.32 | length 64.5
  Top Layer w0.127: U1.B11@90.641,58.395 91.032,58.785 91.032,59.508 91.746,60.222 91.746,60.999 92.49,61.743 92.49,63.158 92.185,63.462 v1(91.785,63.462) ; U26.32@114.435,47.249 v1(115.212,47.249) 116.495,45.966 R141.1@117.064,45.966 ; U25.32@114.435,68.737 115.415,68.737 116.594,67.558 116.96,67.558 R32.1@117.064,67.454
  Signal Layer 3 w0.127: v1(93.538,69.782) 96.974,69.782 97.522,69.235 114.918,69.235 v1(115.82,68.333)
  Signal Layer 6 w0.127: v1(91.785,63.462) 91.785,64 93.538,65.753 v1(93.538,69.782) ; v1(115.212,47.249) 115.212,52.779 116.493,54.06 116.493,67.66 v1(115.82,68.333)
MCU_GPIO156: R58.2 U1.A11 | length 21
  Top Layer w0.127: U1.A11@90.641,59.195 90.641,59.845 91.283,60.487 v1(91.283,61.653) ; v1(105.283,67.945) 105.778,68.44 106.205,68.44 R58.2@106.294,68.53
  Bottom w0.127: v1(91.283,61.653) 91.682,61.653 93.161,63.132 93.175,63.132 93.842,63.799 94.211,63.799 94.738,63.271 98.178,63.271 102.852,67.945 v1(105.283,67.945)
MCU_GPIO157: R112.2 R120.1 U1.E10 | length 37.9
  Top Layer w0.127: U1.E10@89.841,55.995 v2(90.241,56.395) ; v1@105.355,70.136 105.759,69.732 106.294,69.732 R120.1@106.227,69.664
  Signal Layer 3 w0.127: v1(88.207,69.581) 89.219,70.593 93.149,70.593 93.695,71.14 104.374,71.14 v1(105.334,70.18)
  Signal Layer 6 w0.127: v1@88.292,69.496 86.165,67.369 86.165,63.212 86.366,63.012 87.483,63.012 87.981,62.514 87.981,60.244 89.834,58.391 89.834,58.159 89.835,57.032 ; 89.834,57.031 89.834,56.802 v2(90.241,56.395)
  Bottom w0.127: R112.2@104.45,71.245 104.45,70.658 104.927,70.18 v1(105.334,70.18)
MCU_GPIO158: R87.2 U1.D10 | length 25.4
  Top Layer w0.127: U1.D10@89.841,56.795 v2(90.241,57.195) ; v1(104.699,66.523) 105.489,66.523 R87.2@106.294,67.327
  Signal Layer 3 w0.127: v1(89.785,61.551) 89.846,61.612 90.134,61.612 90.777,62.254 90.777,63.508 94.218,66.949 104.273,66.949 v1(104.699,66.523)
  Bottom w0.127: v1(89.785,61.551) 90.15,61.186 90.15,61.18 90.28,61.049 90.28,60.191 90.648,59.824 90.648,57.601 v2(90.241,57.195)
MCU_GPIO159: R86.2 U1.C10 | length 28.9
  Top Layer w0.127: U1.C10@89.841,57.595 v2(90.241,57.995) ; v1(108.85,64.254) R86.2@108.85,65.229
  Top Layer w0.159: R86.2@108.825,65.254 R86.2@108.85,65.229
  Signal Layer 3 w0.127: v1(89.746,60.838) 91.156,60.838 92.401,62.082 92.401,64.485 94.407,66.491 96.146,66.491 97.797,64.84 104.413,64.84 104.962,65.388 107.716,65.388 108.461,64.643 v1(108.85,64.254)
  Signal Layer 6 w0.127: v1(89.746,60.838) 90.241,60.343 v2(90.241,57.995)
MCU_GPIO160: R84.2 U1.B10 | length 28.4
  Top Layer w0.127: U1.B10@89.841,58.395 90.246,58.799 90.246,59.926 90.788,60.468 90.788,61.963 91.187,62.362 v1(91.221,62.362) ; v1(110.069,64.254) R84.2@110.069,65.221
  Top Layer w0.159: R84.2@110.036,65.254 R84.2@110.069,65.221
  Signal Layer 3 w0.127: v1(91.221,62.362) 91.221,63.629 94.312,66.72 96.241,66.72 97.892,65.069 104.319,65.069 104.87,65.62 108.703,65.62 v1(110.069,64.254)
MCU_GPIO161: R83.2 U1.E9 | length 38.4
  Top Layer w0.127: U1.E9@89.041,55.995 v2(89.441,56.395) ; v1(111.201,64.364) R83.2@111.201,65.209
  Top Layer w0.159: R83.2@111.201,65.209 R83.2@111.247,65.254
  Signal Layer 3 w0.127: v1(87.01,62.492) 87.067,62.435 87.363,62.435 87.753,62.046 87.753,60.548 88.371,59.93 90.895,59.93 92.871,61.906 92.871,63.31 93.588,64.028 94.99,64.028 95.535,64.572 97.419,64.572 97.608,64.383 101.393,64.383 102.181,63.596 110.433,63.596 v1(111.201,64.364)
  Signal Layer 6 w0.127: v1(87.01,62.492) 87.361,62.492 87.753,62.101 87.753,60.149 88.819,59.083 88.819,57.017 v2(89.441,56.395)
MCU_GPIO162: R115.1 R127.2 U1.A8 | length 35.8
  Top Layer w0.127: U1.A8@88.241,59.195 88.205,59.231 88.205,60.715 v1(88.642,61.151) ; v1(105.512,64.846) 106.904,66.238 106.904,73.932 R115.1@106.294,74.541
  Signal Layer 3 w0.127: v1@88.806,61.087 89.734,60.159 90.8,60.159 92.63,61.988 92.63,64.391 94.502,66.263 96.052,66.263 97.703,64.612 104.508,64.612 104.959,65.062 105.236,65.062 105.451,64.846 v1(105.512,64.846)
  Bottom w0.127: v1(105.512,64.846) 106.528,64.846 R127.2@106.604,64.922
MCU_GPIO163: R114.1 U1.B8 | length 32.6
  Top Layer w0.127: U1.B8@88.241,58.395 87.851,58.785 87.851,59.931 87.977,60.057 87.977,61.858 v1(88.751,62.632) ; v1(105.181,74.752) 105.181,74.066 105.792,73.455 106.283,73.455 R114.1@106.309,73.43
  Signal Layer 3 w0.127: v1(90.78,72.06) 91.542,72.822 92.196,73.477 97.339,73.477 98.475,74.612 104.925,74.612 105.065,74.752 v1(105.181,74.752)
  Signal Layer 6 w0.127: v1(88.751,62.632) 88.751,62.64 89.027,62.916 89.027,70.307 v1(90.78,72.06)
MCU_GPIO164: R88.1 R119.1 U1.C8 | length 31
  Top Layer w0.127: v2(87.841,57.995) U1.C8@88.241,57.595 ; v1(104.826,68.529) 104.826,71.217 105.745,72.136 R119.1@106.294,72.136
  Signal Layer 3 w0.127: v1(88.54,63.329) 89.048,63.837 89.048,64.835 91.847,67.634 104.021,67.634 104.826,68.439 v1(104.826,68.529)
  Bottom w0.127: v2(87.841,57.995) 87.841,58.031 88.045,58.234 88.045,62.834 v1(88.54,63.329) ; R88.1@104.334,69.52 104.349,69.504 104.349,69.006 v1(104.826,68.529)
MCU_GPIO165: R126.1 R128.2 U1.F6 | length 63.4
  Top Layer w0.127: v2(86.241,55.595) U1.F6@86.641,55.195 ; v1(113.94,78.366) 113.94,77.501 R126.1@114.217,77.224
  Signal Layer 3 w0.127: v1(88.864,77.368) 91.948,77.368 92.907,78.328 101.032,78.328 101.35,78.01 112.376,78.01 112.878,78.511 113.678,78.511 113.823,78.366 v1(113.94,78.366)
  Signal Layer 6 w0.127: v2(86.241,55.595) 86.648,56.001 86.648,58.221 85.506,59.362 85.506,62.079 84.003,63.582 84.003,68.636 85.268,69.901 85.268,76.62 86.27,77.622 88.61,77.622 v1(88.864,77.368)
  Bottom w0.127: v1(113.94,78.366) 114.938,77.368 120.872,77.368 121.217,77.714 R128.2@122.115,77.714
MCU_GPIO166: R113.2 R116.1 U1.B5 | length 57.8
  Top Layer w0.127: U1.B5@85.841,58.395 85.441,58.795 85.441,59.521 85.111,59.851 85.111,61.932 v1(86.711,63.532) ; v1(115.032,78.29) 115.032,78.261 115.286,78.007 R116.1@115.286,77.146
  Signal Layer 3 w0.127: v1(90.957,77.851) 91.663,78.556 100.77,78.556 101.168,78.954 101.868,78.954 102.584,78.239 112.282,78.239 112.879,78.836 114.486,78.836 v1(115.032,78.29)
  Signal Layer 6 w0.127: v1(86.711,63.532) 88.718,65.539 88.718,70.826 90.299,72.407 90.299,73.764 92.241,75.706 92.241,76.639 91.029,77.851 v1(90.957,77.851)
  Bottom w0.127: v1(115.032,78.29) 115.725,77.597 120.777,77.597 R113.2@122.118,78.938
MCU_GPIO167: R111.1 R117.1 U1.E5 | length 62.9
  Top Layer w0.127: v2(85.441,56.395) U1.E5@85.841,55.995 ; R111.1@116.469,82.067 116.469,78.784 v1(116.48,78.772) R117.1@116.48,77.301
  Signal Layer 6 w0.127: v2(85.441,56.395) 85.048,56.789 85.048,58.287 84.883,58.452 84.883,62.056 83.346,63.593 83.346,70.704 84.811,72.168 84.811,74.861 83.587,76.084 83.587,77.828 84.639,78.88 90.97,78.88 91.897,79.807 115.446,79.807 v1(116.48,78.772)
MCU_GPIO168: R89.1 R118.1 U1.F5 | length 64.8
  Top Layer w0.127: v2(85.441,55.595) U1.F5@85.841,55.195 ; R118.1@117.618,77.416 117.598,77.436 v1(117.598,78.188) 117.942,78.532 R89.1@117.942,82.067
  Signal Layer 6 w0.127: v2(85.441,55.595) 85.835,55.989 85.835,58.369 85.217,58.987 85.217,62.045 83.574,63.688 83.574,70.609 85.039,72.074 85.039,74.955 83.816,76.179 83.816,77.734 84.733,78.651 96.28,78.651 97.176,79.547 114.512,79.547 115.871,78.188 v1(117.598,78.188)
MCU_GPIO222/TDI: EC1.8 U1.T12 U7.18 | length 116.3
  Top Layer w0.127: v1(91.057,40.197) 91.441,40.582 U1.T12@91.441,47.195
  Signal Layer 3 w0.127: v1(80.306,65.1) 75.032,59.826 75.032,58.861 68.044,51.874 49.257,51.874 46.736,49.352 46.736,41.783 51.41,37.109 51.41,33.909 53.528,31.79 54.345,31.79 v1(54.381,31.826) 54.458,31.75 62.489,31.75 70.833,40.094 76.512,40.094 77.432,39.174 83.726,39.174 84.301,38.599 89.055,38.599 90.48,40.024 90.829,40.024 v1@90.86,40.054
  Bottom w0.127: EC1.8@54.357,28.836 54.357,31.802 v1(54.381,31.826) ; v1(80.306,65.1) 81.74,65.1 82.044,64.796 U7.18@83.242,64.796
MCU_GPIO223/TDO: EC1.6 U1.R12 U7.8 | length 122.9
  Top Layer w0.127: v1(89.43,40.429) 89.464,40.394 90.036,40.394 90.705,39.726 91.338,39.726 91.832,40.219 91.832,47.604 U1.R12@91.441,47.995
  Signal Layer 3 w0.127: v1(78.988,67.576) 79.624,68.212 81.178,68.212 82.194,67.196 82.194,65.678 75.717,59.201 75.717,58.577 68.328,51.188 49.643,51.188 47.422,48.967 47.422,42.067 52.121,37.368 52.121,35.55 52.923,34.747 v1(52.959,34.747) 53.391,34.315 64.084,34.315 70.554,40.786 76.823,40.786 77.749,39.859 84.01,39.859 84.585,39.285 88.286,39.285 v1(89.43,40.429)
  Bottom w0.127: v1(52.959,34.747) 52.997,34.709 52.997,31.61 53.584,31.023 EC1.6@53.584,28.923 ; U7.8@77.642,68.046 78.518,68.046 v1(78.988,67.576)
MCU_TCK: EC1.5 U1.R13 U7.14 | length 119.3
  Top Layer w0.127: EC1.5@53.557,28.836 53.557,33.323 53.696,33.462 v1(53.696,33.579) ; U1.R13@92.241,47.995 92.632,47.604 92.632,44.46 92.993,44.098 92.993,43.72 92.43,43.157 v1@92.426,43.157
  Signal Layer 3 w0.127: v1(80.811,66.015) 80.826,65.999 80.826,64.956 75.26,59.391 75.26,58.767 68.139,51.645 49.454,51.645 46.965,49.156 46.965,41.878 51.664,37.179 51.664,34.112 52.197,33.579 v1(53.696,33.579) 63.994,33.579 70.738,40.323 71.056,40.323 71.062,40.328 76.601,40.328 77.527,39.402 83.821,39.402 84.396,38.828 88.96,38.828 90.893,40.761 91.663,40.761 92.05,41.148 92.05,42.923 v1@92.361,43.234
  Bottom w0.127: v1(80.811,66.015) 80.811,66.131 80.941,66.262 80.941,66.295 82.042,67.396 U7.14@83.242,67.396
  other v1: 92.338,43.142
MCU_TMS: EC1.3 R202.1 U1.T13 U7.16 | length 119.3
  Top Layer w0.127: v1(52.553,34.036) 52.553,33.95 52.757,33.746 EC1.3@52.757,28.836 ; v1@92.241,44.181 U1.T13@92.241,47.195
  Signal Layer 3 w0.127: v1(52.553,34.036) 64.128,34.036 70.649,40.557 76.728,40.557 77.654,39.631 83.916,39.631 84.49,39.056 88.866,39.056 90.799,40.989 91.494,40.989 91.702,41.198 91.702,43.301 v1(92.32,43.919) ; v1@52.565,34.023 51.892,34.696 51.892,37.273 47.193,41.972 47.193,49.061 49.548,51.416 68.233,51.416 75.489,58.672 75.489,59.296 81.543,65.35 v1@81.543,66.138
  Bottom w0.127: v1@81.543,66.138 83.2,66.138 U7.16@83.242,66.096 ; v1(92.32,43.919) 93.423,43.919 94.078,43.264 94.638,43.264 95.182,43.807 R202.1@95.272,43.807
  other v1: 81.612,66.144
MCU_XRSn: C38.1 EC1.120 R42.1 R44.1 R49.1 R55.1 R82.2 S4.4 TP10.1 U1.G14 | length 84.9
  Top Layer w0.127: U1.G14@93.041,54.395 v2(93.441,54.795) ; S4.4@98.56,81.723 98.917,81.366 99.126,81.366 99.644,80.848 107.064,80.848 107.501,80.411 107.501,80.017 108.251,79.267 108.251,77.299 107.781,76.829 107.471,76.829 107.471,76.834 106.701,77.604 105.304,77.604 105.239,77.538 105.237,77.538 105.125,77.427 105.125,77.425 104.699,76.999 104.699,72.51 104.249,72.06 102.481,72.06 102.006,71.585 R44.1@102.006,71.26 102.006,70.51 102.997,69.519 v1(102.997,68.428) ; TP10.1@99.716,56.877 100.714,55.88 R82.2@101.58,55.88
  Signal Layer 6 w0.127: v1(102.997,68.428) 103.302,68.123 103.302,58.787 102.04,57.525 100.364,57.525 TP10.1@99.716,56.877 101.353,55.241 101.353,50.889 102.438,49.804 103.358,49.804 104.115,49.047 104.115,47.804 104.123,47.796 104.123,44.821 104.115,44.813 104.115,43.437 104.864,42.687 104.864,39.256 v1(104.191,38.583)
  Bottom w0.127: v2(93.441,54.795) 93.505,54.732 93.668,54.732 93.681,54.718 97.924,54.718 99.443,56.237 99.443,56.295 99.497,56.349 99.497,56.659 TP10.1@99.716,56.877 ; EC1.120@102.357,28.836 102.357,35.031 C38.1@102.845,35.519 ; C38.1@103.081,35.282 C38.1@102.845,35.519 ; v1(104.191,38.583) 104.191,36.846 R42.1@104.089,36.744 104.07,36.744 C38.1@102.845,35.519
MID_RXD: U6.13 U7.11 | length 10.9
  Top Layer w0.127: U6.13@74.907,65.343 77.136,65.343 77.445,65.652 77.445,66.751 78.74,68.047 80.061,68.047 v1(80.366,67.742)
  Bottom w0.127: v1(80.366,67.742) 81.065,68.441 81.97,69.346 U7.11@83.242,69.346
MID_TCK_SWDCLK: U6.12 U7.6 | length 4.5
  Top Layer w0.127: U6.12@74.907,64.708 75.919,64.708 76.083,64.872 v1(76.2,64.872)
  Bottom w0.127: v1(76.2,64.872) 76.2,64.971 76.009,65.162 76.009,66.027 76.726,66.743 77.639,66.743 U7.6@77.642,66.746
MID_TDI: U6.15 U7.2 | length 6.4
  Top Layer w0.127: U6.15@74.907,66.613 74.993,66.699 v1(76.05,66.699)
  Signal Layer 3 w0.127: v1(76.05,66.699) 76.077,66.726 76.773,66.726 78.853,64.646 v1(78.853,64.479)
  Bottom w0.127: U7.2@77.642,64.146 77.682,64.186 78.56,64.186 v1(78.853,64.479)
MID_TDO_SWO: U6.10 U7.12 | length 12.1
  Top Layer w0.127: U6.10@74.907,63.438 76.018,63.438 76.261,63.195 v1(76.378,63.195)
  Bottom w0.127: v1(76.378,63.195) 76.418,63.155 78.684,63.155 79.553,64.024 79.553,66.294 81.955,68.696 U7.12@83.242,68.696
MID_TMS_JTAG: U6.14 U7.4 | length 3
  Top Layer w0.127: U6.14@74.907,65.978 76.304,65.978 v1(76.454,65.828)
  Bottom w0.127: v1(76.454,65.828) 76.836,65.446 U7.4@77.642,65.446
MID_TXD: U6.11 U7.7 | length 6.7
  Top Layer w0.127: U6.11@74.907,64.073 74.918,64.084 v1(76.073,64.084)
  Bottom w0.127: v1(76.073,64.084) 75.413,64.745 75.413,66.827 75.729,67.144 76.313,67.144 76.565,67.396 U7.7@77.642,67.396
NetB1_2: B1.2 R73.2 R74.1 | length 5.3
  Bottom w0.127: B1.2@128.557,65.783 129.44,65.783 130.415,66.758 R73.2@130.415,68.549 131.633,68.549 R74.1@131.648,68.564
NetB1_3: B1.3 R65.1 | length 2.9
  Bottom w0.127: B1.3@128.557,66.433 129.103,66.433 129.565,66.895 129.565,67.908 129.145,68.329 R65.1@129.145,68.406
NetB1_5: B1.5 R68.1 | length 2.5
  Bottom w0.127: R68.1@132.904,68.406 132.904,67.658 133.478,67.083 B1.5@134.457,67.083
NetB1_8: B1.8 R67.1 | length 2.1
  Bottom w0.127: B1.8@134.576,65.253 B1.8@134.457,65.133 135.776,65.133 R67.1@136.231,64.678
NetC1_1: C1.1 R7.2 U2.96 | length 5.7
  Top Layer w0.127: v1(56.994,71.137) 57.756,71.137 58.833,71.137 R7.2@58.874,71.179
  Bottom w0.159: U2.96@53.535,71.866 56.266,71.866 v1(56.994,71.137)
NetC10_1: C10.1 C11.1 C12.1 U2.87 U2.115 | length 16.6
  Bottom w0.159: U2.87@53.535,68.266 59.249,68.266 62.235,71.252 U2.115@62.235,73.366 62.235,74.843 62.475,75.082 62.69,75.297 62.715,75.322 63.909,75.322 C10.1@65.128,75.322
NetC13_1: C13.1 U2.89 Y1.3 | length 7
  Bottom w0.127: Y1.3@48.752,72.466 48.752,71.934 49.295,71.391 51.134,71.391 51.136,71.393 51.384,71.145 C13.1@51.384,70.799 ; C13.1@51.366,70.781 51.451,70.696 51.451,70.254 52.64,69.066 U2.89@53.535,69.066
NetC14_1: C14.1 U2.88 Y1.1 | length 8.3
  Bottom w0.127: Y1.1@46.825,69.944 47.32,70.438 47.32,70.713 47.6,70.993 C14.1@49.935,70.993 ; C14.1@50.136,70.791 50.136,70.234 51.697,68.674 U2.88@53.54,68.674
NetC15_1: C15.1 R13.1 U2.68 | length 5.5
  Bottom w0.127: C15.1@50.517,62.339 51.145,61.712 52.17,61.712 52.448,61.435 52.448,60.759 52.541,60.666 U2.68@53.535,60.666 ; C15.1@50.517,62.349 R13.1@50.517,63.756
NetC19_1: C19.1 U8.4 | length 3.9
  Top Layer w0.127: U8.4@51.513,63.075 53.282,63.075 53.797,62.56 C19.1@53.797,61.154
NetC39_1: C39.1 U11.3 | length 1.8
  Top Layer w0.159: C39.1@95.481,75.844 C39.1@95.698,75.844 96.013,75.529 U11.3@97.108,75.529
NetC41_2: C41.2 R51.1 U12.2 | length 17.5
  Top Layer w0.127: v1@98.897,77.876 99.11,78.089 99.974,78.089 U12.2@99.995,78.068 ; R51.1@101.19,67.337 101.852,67.337 102.354,66.835 v1(102.354,66.262) 102.764,65.853 C41.2@103.327,65.853
  Signal Layer 6 w0.127: v1(98.731,77.78) 98.772,77.78 100.914,75.637 100.914,67.702 v1(102.354,66.262) ; v1@102.354,66.199 v1@102.508,66.199
NetC42_2: C42.2 R54.1 U12.4 | length 16.9
  Top Layer w0.127: v1(99.132,76.791) 99.43,77.089 U12.4@100.008,77.089 ; R54.1@99.997,67.337 99.997,66.373 100.533,65.837 101.127,65.837 C42.2@101.168,65.878 101.438,65.608 v1(102.133,65.608)
  Signal Layer 6 w0.127: v1(99.132,76.791) 100.686,75.237 100.686,67.056 v1(102.133,65.608)
NetC48_1: C48.1 R30.1 R95.2 R97.2 | length 10.2
  Bottom w0.127: C48.1@139.878,42.228 139.878,42.824 140.802,43.749 142.5,43.749 142.688,43.56 142.688,43.164 142.708,43.144 R95.2@142.708,42.109 ; R97.2@142.708,45.687 143.597,45.687 144.435,44.848 144.435,44.213 143.366,43.144 R30.1@142.713,43.144
NetC48_2: C48.2 C49.1 L1.2 R2.1 R30.2 R94.2
NetC50_1: C50.1 R102.1 R206.2 U15.1 | length 7.9
  Top Layer w0.127: v1(139.09,48.082) 140.837,49.828 141.091,49.828 v1(141.173,49.911)
  Bottom w0.127: U15.1@138.31,47.507 138.498,47.507 139.072,48.082 v1(139.09,48.082) ; C50.1@139.762,50.906 139.908,50.759 R206.2@141.508,50.759 ; v1(141.173,49.911) 141.508,50.246 R206.2@141.508,50.759 ; R102.1@141.508,51.96 R206.2@141.508,50.759
NetC50_2: C50.2 C125.1 L2.2 R101.1 R102.2
NetC52_2: C52.2 R99.1 U15.8 | length 4.2
  Bottom w0.127: C52.2@133.299,47.668 133.299,46.463 133.341,46.505 133.716,46.505 133.718,46.507 U15.8@136.235,46.507
NetC63_2: C63.2 R199.1 | length 1.6
  Top Layer w0.127: C63.2@76.024,50.035 76.024,48.7 R199.1@76.21,48.514
NetC87_2: C87.2 C88.2 J5.5 | length 8.2
  Top Layer w0.159: v1(121.615,71.196) 121.692,71.273 122.043,71.273 122.372,71.602 124.367,71.602 J5.5@124.544,71.778
  Bottom w0.127: v1(121.615,71.196) 122.411,71.992 124.33,71.992 C88.2@124.774,72.437 124.749,72.462 C87.2@124.749,73.736
NetC89_1: C89.1 C90.1 U25.2 | length 4.3
  Top Layer w0.127: U25.2@115.085,69.887 116.868,69.887 C90.1@117.049,69.707 ; C90.1@117.049,69.73 C90.1@117.049,69.707 ; C89.1@117.064,68.526 117.049,68.541 C90.1@117.049,69.707 ; C89.1@117.064,68.674 117.064,69.692 C90.1@117.049,69.707
NetC95_2: C95.2 C96.2 J5.6 | length 5.7
  Top Layer w0.159: v1@121.869,70.536 121.892,70.559 124.344,70.559 J5.6@124.544,70.758
  Bottom w0.127: v1(121.904,70.499) 122.576,71.171 C96.2@123.25,71.171 ; C95.2@123.35,69.901 C96.2@123.35,71.071
  Bottom w0.159: C96.2@123.25,71.171 C96.2@123.35,71.071
NetC97_1: C97.1 C98.1 R131.2 U25.3 | length 6
  Top Layer w0.305: U25.3@115.085,70.387 115.099,70.401 v1@116.013,70.401
  Bottom w0.305: v1(116.002,70.383) 116.715,69.67 C97.1@116.715,67.879 ; C97.1@117.06,68.153 117.085,68.128 C98.1@118.254,68.128 119.115,68.128 R131.2@119.249,67.995
NetC99_1: C99.1 C100.1 R134.1 U25.17 | length 5.8
  Top Layer w0.305: U25.17@110.285,72.887 110.285,75.512 110.74,75.966 C99.1@110.74,75.991 111.989,75.991 112.137,76.139 C100.1@112.137,76.216 112.981,76.216 R134.1@113.081,76.316
NetC102_2: C102.2 C104.2 J6.5 | length 6
  Top Layer w0.159: v1@121.844,50.317 121.92,50.241 122.201,50.241 122.549,49.892 J6.5@125.015,49.892
  Bottom w0.159: v1(121.817,50.278) 122.296,50.757 122.7,50.757 C104.2@122.92,50.978 ; C104.2@122.947,51.017 C102.2@122.947,52.229
NetC105_1: C105.1 C106.1 U26.2 | length 3.2
  Top Layer w0.155: U26.2@115.085,48.399 C106.1@117.064,48.399 C105.1@117.064,47.185
NetC111_2: C111.2 C112.2 J6.6 | length 6.3
  Top Layer w0.159: v1(121.753,49.213) 122.093,48.872 J6.6@125.015,48.872
  Bottom w0.159: C112.2@122.947,48.593 122.373,48.593 v1(121.753,49.213) 122.346,49.805 C111.2@122.947,49.805
NetC113_1: C113.1 C114.2 R166.2 U26.3 | length 6.3
  Top Layer w0.305: U26.3@115.085,48.899 115.097,48.887 v1(115.86,48.887)
  Bottom w0.305: C113.1@114.757,48.908 118.795,48.908 C114.2@118.914,48.789 119.52,48.183 R166.2@119.96,48.183
NetC115_1: C115.1 C116.2 R168.1 U26.17 | length 4.3
  Top Layer w0.305: v1(109.669,51.725) 109.745,51.649 109.861,51.649 110.11,51.399 U26.17@110.285,51.399
  Bottom w0.305: R168.1@106.172,51.757 109.637,51.757 v1(109.669,51.725)
NetC118_2: C118.2 R200.1 | length 5.2
  Top Layer w0.127: C118.2@85.344,43.93 86.762,42.512 86.762,40.534 v1(86.741,40.513)
  Bottom w0.127: v1(86.741,40.513) 87.073,40.845 87.073,41.287 R200.1@87.274,41.488
NetC119_2: C119.2 R201.1 | length 1.6
  Top Layer w0.127: C119.2@76.035,51.805 76.035,53.104 R201.1@76.239,53.308
NetC121_1: C121.1 U23.5 | length 3.1
  Top Layer w0.127: v1(77.267,36.703) 77.368,36.703 77.778,37.112 78.496,37.112 U23.5@78.569,37.186
  Bottom w0.127: C121.1@77.137,38.257 77.267,38.127 v1(77.267,36.703)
